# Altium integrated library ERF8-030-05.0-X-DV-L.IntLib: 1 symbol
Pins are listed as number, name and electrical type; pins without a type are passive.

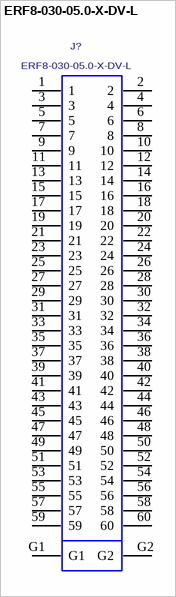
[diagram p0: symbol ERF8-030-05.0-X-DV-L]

## ERF8-030-05.0-X-DV-L
designator J?
0.8mm Edge Rate Socket Assembly, Double Vertical Row, 60 Pins.; MANUFACTURER: SAMTEC
footprint ERF8-030-05.0-X-DV-L
pins: 1, 2, 3, 4, 5, 6, 7, 8, 9, 10, 11, 12, 13, 14, 15, 16, 17, 18, 19, 20, 21, 22, 23, 24, 25, 26, 27, 28, 29, 30, 31, 32, 33, 34, 35, 36, 37, 38, 39, 40, 41, 42, 43, 44, 45, 46, 47, 48, 49, 50, 51, 52, 53, 54, 55, 56, 57, 58, 59, 60, G1, G2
